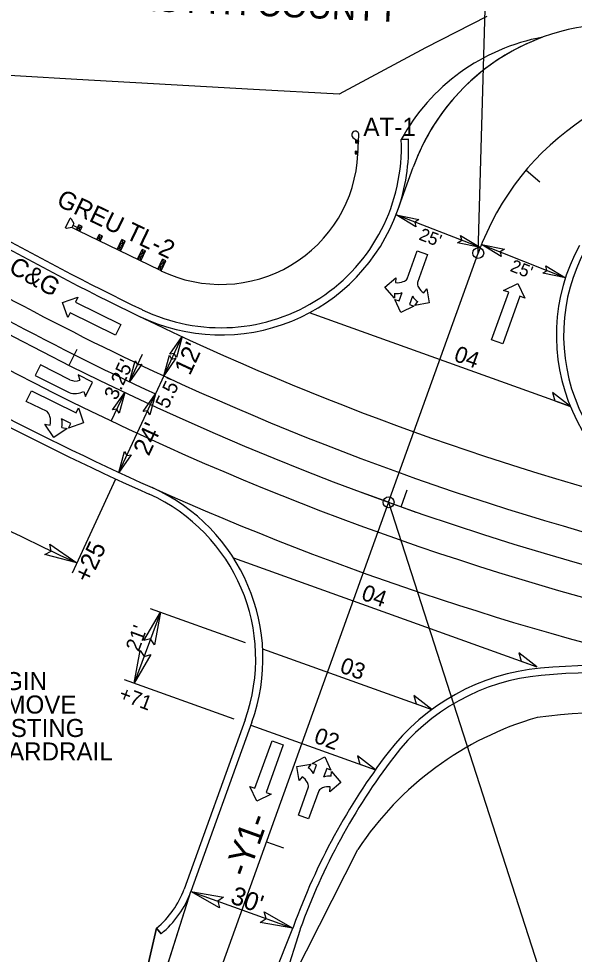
# Model space of a CAD drawing. Extents: x 1616561 to 1622460, y 896726 to 899651.
# Drawn here: x 1619426.3 to 1619580.2, y 897963.2 to 898222.4 of the extents above; entities that cross this region are included whole.
import ezdxf

# ---------------------------------------------------------------- set-up
doc = ezdxf.new("R2010")
doc.units = 0
for name, color, linetype in [('Old_Level_3', 7, 'Continuous'), ('Prop Dimension', 7, 'Continuous'), ('Prop DSN Text', 7, 'Continuous'), ('Prop Guardrail', 7, 'Continuous'), ('Prop Guardrail Anchor Unit CELL', 7, 'Continuous'), ('Prop Horizontal Alignment', 7, 'Continuous'), ('Prop Horizontal Alignment Tick Small', 7, 'Continuous'), ('Prop Lane Arrow CELL', 7, 'Continuous'), ('Prop North Arrow NAD83 for Plan Sheets CELL', 7, 'Continuous'), ('Prop Rem of Exist Asph Pvmt', 7, 'Continuous'), ('Prop Shade Light', 7, 'Continuous'), ('Prop Superelevation  Arrow CELL', 7, 'Continuous'), ('Prop Superelevation Label', 7, 'Continuous'), ('Prop Terminator CELL', 7, 'Continuous'), ('Scratch_Level_1', 7, 'Continuous'), ('Sheet Cutting Line CELL', 7, 'Continuous'), ('Sheet North Arrow CELL', 7, 'Continuous'), ('Sheet Sticker Preliminary CELL', 7, 'Continuous')]:
    doc.layers.add(name, color=color, linetype=linetype)

msp = doc.modelspace()

# ---------------------------------------------------------------- linework, layer by layer
at = {"layer": 'Old_Level_3'}
msp.add_line((1619466.5, 898123.48), (1619464.18, 898118.49), dxfattribs=at)
for radius, start, end in [(791.25, 230.78618, 245.11013), (808.75, 229.34838, 255.58792), (796.75, 230.7866, 245.11013), (779.25, 244.13867, 256.29422), (791.25, 245.11013, 270), (820.75, 245.81358, 257.75937)]:
    msp.add_arc((1619799.51, 898841.24), radius, start, end, dxfattribs=at)
at = {"layer": 'Prop Dimension'}
for p, q in [((1619554.16, 898159.09), (1619530.83, 898168.07)), ((1619554.49, 898159.91), (1619577.71, 898150.66)), ((1619466.5, 898123.48), (1619471.55, 898134.37)), ((1619457.02, 898121.86), (1619460.56, 898129.47)), ((1619451.96, 898110.94), (1619455.66, 898118.91)), ((1619454.08, 898096.72), (1619464.18, 898118.49)), ((1619441.18, 898068.92), (1619453.24, 898094.91)), ((1619474.01, 897980.62), (1619502.24, 897970.46))]:
    msp.add_line(p, q, dxfattribs=at)
msp.add_arc((1619799.51, 898841.24), 848.4, 239.73865, 245.11013, dxfattribs=at)
at = {"layer": 'Prop Guardrail'}
msp.add_line((1619496.51, 897945.53), (1619520.23, 897992.28), dxfattribs=at)
for centre, radius, start, end in [((1619482.29, 898186.82), 38, 244.1387, 357.2224), ((1619594.68, 897943.19), 89.17, 106.1694, 146.5997), ((1619590.52, 897870.95), 159.23, 78.786, 97.4583)]:
    msp.add_arc(centre, radius, start, end, dxfattribs=at)
at = {"layer": 'Prop Guardrail Anchor Unit CELL'}
for p, q in [((1619518.88, 898189.52), (1619519.81, 898188.75)), ((1619520.42, 898188.52), (1619520.5, 898190.24)), ((1619519.62, 898188.76), (1619519.59, 898188.06)), ((1619520.43, 898188.72), (1619519.59, 898188.06)), ((1619519.59, 898188.06), (1619520.39, 898188.02)), ((1619520.43, 898188.72), (1619519.62, 898188.76)), ((1619520.39, 898188.02), (1619519.62, 898188.76)), ((1619520.43, 898188.72), (1619520.08, 898188.74)), ((1619520.43, 898188.72), (1619520.08, 898188.74)), ((1619520.25, 898184.98), (1619520.42, 898188.52)), ((1619520.39, 898188.02), (1619520.43, 898188.72)), ((1619520.42, 898188.59), (1619520.41, 898188.46)), ((1619520.42, 898188.59), (1619520.41, 898188.46)), ((1619519.47, 898185.72), (1619519.44, 898185.02)), ((1619520.28, 898185.68), (1619519.44, 898185.02)), ((1619519.44, 898185.02), (1619520.25, 898184.98)), ((1619520.28, 898185.68), (1619519.47, 898185.72)), ((1619520.25, 898184.98), (1619519.47, 898185.72)), ((1619520.25, 898184.98), (1619520.28, 898185.68)), ((1619439.29, 898164.5), (1619440.58, 898167.14)), ((1619440.85, 898167.01), (1619440.58, 898167.14)), ((1619440.85, 898167.01), (1619441.54, 898165.72)), ((1619439.57, 898164.36), (1619439.29, 898164.5)), ((1619441, 898164.62), (1619439.57, 898164.36)), ((1619441.54, 898165.72), (1619441, 898164.62)), ((1619442.32, 898163.98), (1619441, 898164.62)), ((1619441.32, 898165.27), (1619442.64, 898164.63)), ((1619442.32, 898163.97), (1619442.98, 898165.34)), ((1619443.88, 898164.9), (1619442.32, 898163.97)), ((1619443.22, 898163.53), (1619442.32, 898163.97)), ((1619442.77, 898163.75), (1619465.27, 898152.85)), ((1619443.88, 898164.9), (1619442.98, 898165.34)), ((1619443.22, 898163.53), (1619442.98, 898165.34)), ((1619443.22, 898163.53), (1619443.88, 898164.9)), ((1619447.94, 898161.24), (1619448.61, 898162.61)), ((1619449.51, 898162.17), (1619447.94, 898161.24)), ((1619448.84, 898160.81), (1619447.94, 898161.24)), ((1619449.51, 898162.17), (1619448.61, 898162.61)), ((1619448.84, 898160.81), (1619448.61, 898162.61)), ((1619448.84, 898160.81), (1619449.51, 898162.17)), ((1619453.57, 898158.52), (1619454.89, 898161.25)), ((1619454.23, 898159.88), (1619455.79, 898160.81)), ((1619454.47, 898158.08), (1619455.79, 898160.81)), ((1619455.79, 898160.81), (1619454.89, 898161.25)), ((1619454.89, 898161.25), (1619455.13, 898159.45)), ((1619455.13, 898159.45), (1619453.57, 898158.52)), ((1619454.47, 898158.08), (1619453.57, 898158.52)), ((1619455.13, 898159.45), (1619454.23, 898159.88)), ((1619454.47, 898158.08), (1619454.23, 898159.88)), ((1619459.19, 898155.79), (1619460.52, 898158.52)), ((1619461.42, 898158.09), (1619460.52, 898158.52)), ((1619460.52, 898158.52), (1619460.75, 898156.72)), ((1619460.75, 898156.72), (1619459.19, 898155.79)), ((1619460.09, 898155.35), (1619459.19, 898155.79)), ((1619459.85, 898157.16), (1619461.42, 898158.09)), ((1619460.75, 898156.72), (1619459.85, 898157.16)), ((1619460.09, 898155.35), (1619459.85, 898157.16)), ((1619460.09, 898155.35), (1619461.42, 898158.09)), ((1619464.82, 898153.06), (1619466.14, 898155.8)), ((1619467.04, 898155.36), (1619466.14, 898155.8)), ((1619466.14, 898155.8), (1619466.38, 898153.99)), ((1619466.38, 898153.99), (1619464.82, 898153.06)), ((1619465.72, 898152.63), (1619464.82, 898153.06)), ((1619465.48, 898154.43), (1619467.04, 898155.36)), ((1619466.38, 898153.99), (1619465.48, 898154.43)), ((1619465.72, 898152.63), (1619465.48, 898154.43)), ((1619465.72, 898152.63), (1619467.04, 898155.36))]:
    msp.add_line(p, q, dxfattribs=at)
msp.add_ellipse((1619519.51, 898190.29), major_axis=(-0.992, 0.048), ratio=0.995379, start_param=3.141593, end_param=7.214552, dxfattribs=at)
at = {"layer": 'Prop Horizontal Alignment'}
for p, q in [((1619532.25, 898188.96), (1619534.24, 898189.05)), ((1619449.19, 897903.92), (1619464.48, 897970.44)), ((1619464.48, 897970.44), (1619465.75, 897968.9))]:
    msp.add_line(p, q, dxfattribs=at)
for centre, radius, start, end in [((1619581.52, 898162.12), 56.11, 100.4391, 151.4276), ((1619482.29, 898186.82), 52, 340.2164, 2.4498), ((1619448.6, 897989.76), 27, 309.4241, 340.2164)]:
    msp.add_arc(centre, radius, start, end, dxfattribs=at)
at = {"layer": 'Prop Horizontal Alignment Tick Small'}
for p, q in [((1619534.24, 898189.05), (1619532.25, 898188.96)), ((1619488.99, 898028.18), (1619472.13, 897981.29)), ((1619465.75, 897968.9), (1619464.48, 897970.44)), ((1619504.12, 897969.79), (1619496.51, 897945.53)), ((1619504.3, 897970.28), (1619504.12, 897969.79))]:
    msp.add_line(p, q, dxfattribs=at)
for centre, radius, start, end in [((1619799.51, 898841.24), 777.25, 229.34838, 244.13867), ((1619799.51, 898841.24), 822.75, 230.21163, 245.81358), ((1619482.29, 898186.82), 50, 244.1387, 2.4498), ((1619627.2, 898134.7), 50, 151.351, 256.2942), ((1619441.94, 898045.1), 50, 340.2164, 65.8136), ((1619576.32, 897982.74), 58, 95.2664, 142.7094), ((1619587.34, 897863.24), 178, 77.7594, 95.2664), ((1619671.79, 897910.03), 178, 142.7094, 160.2164), ((1619448.6, 897989.76), 25, 309.4241, 340.2164)]:
    msp.add_arc(centre, radius, start, end, dxfattribs=at)
at = {"layer": 'Prop Lane Arrow CELL'}
for p, q in [((1619533.88, 898150.39), (1619536.67, 898158.14)), ((1619536.67, 898158.14), (1619539.51, 898157.12)), ((1619539.51, 898157.12), (1619536.71, 898149.32)), ((1619527.72, 898148.1), (1619530.75, 898150.64)), ((1619530.75, 898150.64), (1619530.69, 898149.31)), ((1619530.35, 898145.03), (1619527.72, 898148.1)), ((1619560.59, 898147.16), (1619564.57, 898149.07)), ((1619564.57, 898149.07), (1619566.51, 898145.02)), ((1619438.45, 898143.81), (1619442.69, 898145.29)), ((1619442.69, 898145.29), (1619442.03, 898143.94)), ((1619530.41, 898146.36), (1619530.35, 898145.03)), ((1619531.67, 898144.25), (1619532.53, 898146.63)), ((1619535.35, 898145.56), (1619534.51, 898143.22)), ((1619538.49, 898146.51), (1619539.29, 898147.57)), ((1619539.29, 898147.57), (1619539.97, 898143.69)), ((1619557.26, 898133.48), (1619562, 898146.65)), ((1619565.1, 898145.53), (1619560.36, 898132.36)), ((1619562, 898146.65), (1619560.59, 898147.16)), ((1619566.51, 898145.02), (1619565.1, 898145.53)), ((1619439.91, 898139.64), (1619438.45, 898143.81)), ((1619442.03, 898143.94), (1619454.59, 898137.76)), ((1619532.16, 898141.01), (1619530.48, 898144.67)), ((1619530.48, 898144.67), (1619531.67, 898144.25)), ((1619535.71, 898142.79), (1619532.16, 898141.01)), ((1619534.51, 898143.22), (1619535.71, 898142.79)), ((1619536.03, 898142.99), (1619536.83, 898144.05)), ((1619539.97, 898143.69), (1619536.03, 898142.99)), ((1619440.57, 898140.98), (1619439.91, 898139.64)), ((1619453.13, 898134.8), (1619440.57, 898140.98)), ((1619454.59, 898137.76), (1619453.13, 898134.8)), ((1619560.36, 898132.36), (1619557.26, 898133.48)), ((1619432.31, 898126.51), (1619430.84, 898123.56)), ((1619440.5, 898122.43), (1619432.31, 898126.51)), ((1619430.84, 898123.56), (1619440.28, 898118.85)), ((1619446.79, 898121.7), (1619442.78, 898123.75)), ((1619442.78, 898123.75), (1619443.25, 898122.34)), ((1619428.38, 898116.41), (1619429.83, 898119.37)), ((1619429.83, 898119.37), (1619442.21, 898113.28)), ((1619444.78, 898117.79), (1619446.79, 898121.7)), ((1619444.31, 898119.19), (1619444.78, 898117.79)), ((1619434.16, 898113.57), (1619428.38, 898116.41)), ((1619442.21, 898113.28), (1619442.88, 898114.63)), ((1619442.88, 898114.63), (1619444.27, 898110.43)), ((1619440.76, 898110.32), (1619438.2, 898111.58)), ((1619436.06, 898106.44), (1619433.58, 898110.12)), ((1619433.58, 898110.12), (1619435.01, 898109.86)), ((1619439.74, 898108.93), (1619436.06, 898106.44)), ((1619438.26, 898109.21), (1619439.74, 898108.93)), ((1619444.27, 898110.43), (1619440.09, 898108.97)), ((1619440.09, 898108.97), (1619440.76, 898110.32)), ((1619491.74, 898009.2), (1619496.48, 898022.37)), ((1619499.59, 898021.26), (1619494.85, 898008.08)), ((1619496.48, 898022.37), (1619499.59, 898021.26)), ((1619503.3, 898015.21), (1619507.23, 898015.92)), ((1619507.23, 898015.92), (1619506.44, 898014.86)), ((1619507.56, 898016.11), (1619511.1, 898017.89)), ((1619508.75, 898015.68), (1619507.56, 898016.11)), ((1619507.91, 898013.34), (1619508.75, 898015.68)), ((1619511.1, 898017.89), (1619512.79, 898014.23)), ((1619503.98, 898011.34), (1619503.3, 898015.21)), ((1619511.6, 898014.66), (1619510.74, 898012.27)), ((1619512.79, 898014.23), (1619511.6, 898014.66)), ((1619512.86, 898012.55), (1619512.92, 898013.87)), ((1619512.92, 898013.87), (1619515.55, 898010.8)), ((1619504.78, 898012.4), (1619503.98, 898011.34)), ((1619515.55, 898010.8), (1619512.51, 898008.27)), ((1619492.28, 898005.66), (1619490.33, 898009.71)), ((1619490.33, 898009.71), (1619491.74, 898009.2)), ((1619494.85, 898008.08), (1619496.26, 898007.57)), ((1619503.75, 898001.78), (1619506.56, 898009.58)), ((1619509.39, 898008.51), (1619506.6, 898000.76)), ((1619512.51, 898008.27), (1619512.57, 898009.59)), ((1619496.26, 898007.57), (1619492.28, 898005.66)), ((1619506.6, 898000.76), (1619503.75, 898001.78))]:
    msp.add_line(p, q, dxfattribs=at)
for centre, radius, start, end in [((1619532.04, 898151.74), 2.28, 289.2896, 324.0556), ((1619531.25, 898153.28), 4, 261.8495, 292.7797), ((1619538.98, 898149.24), 2.28, 178.1454, 211.1433), ((1619540.57, 898149.92), 4, 207.6532, 238.8659), ((1619531, 898150.31), 4, 261.4803, 292.37), ((1619538.87, 898147.48), 4, 208.4597, 239.2361), ((1619441.96, 898125.34), 3.28, 243.5163, 293.1745), ((1619441.88, 898123.84), 5.25, 252.1924, 297.5041), ((1619432.51, 898111.66), 2.52, 12.8702, 49.1822), ((1619430.72, 898110.97), 4.43, 345.5068, 16.3603), ((1619433.96, 898110.33), 4.43, 345.388, 16.2666), ((1619504.4, 898011.43), 4, 28.4597, 59.2361), ((1619502.7, 898008.98), 4, 27.6532, 58.8659), ((1619504.29, 898009.66), 2.28, 358.1454, 31.1433), ((1619512.27, 898008.6), 4, 81.4803, 112.37), ((1619511.23, 898007.16), 2.28, 109.2896, 144.0556), ((1619512.02, 898005.63), 4, 81.8495, 112.7797)]:
    msp.add_arc(centre, radius, start, end, dxfattribs=at)
at = {"layer": 'Prop North Arrow NAD83 for Plan Sheets CELL'}
for points in [[(1619579.08, 898114.98), (1619574.12, 898118.9), (1619574.73, 898116.55)], [(1619569.78, 898042.88), (1619564.81, 898046.79), (1619565.43, 898044.44)], [(1619540.7, 898031.02), (1619535.73, 898034.93), (1619536.35, 898032.58)], [(1619525.08, 898014.32), (1619520.11, 898018.23), (1619520.73, 898015.89)]]:
    msp.add_lwpolyline(points, close=True, dxfattribs=at)
at = {"layer": 'Prop Rem of Exist Asph Pvmt'}
for p, q in [((1619555.96, 898223.09), (1619538.96, 898214.39)), ((1619538.96, 898214.39), (1619515.06, 898201.52))]:
    msp.add_line(p, q, dxfattribs=at)
msp.add_lwpolyline([(1619515.06, 898201.52), (1619491.31, 898202.8), (1619473.44, 898203.85), (1619442.37, 898205.63), (1619411.08, 898207.46), (1619398.89, 898207.97)], dxfattribs=at)
at = {"layer": 'Prop Shade Light'}
for p, q in [((1619532.25, 898188.96), (1619534.24, 898189.05)), ((1619531.22, 898169.22), (1619535.56, 898181.28)), ((1619464.48, 897970.44), (1619449.19, 897903.92)), ((1619465.75, 897968.9), (1619464.48, 897970.44))]:
    msp.add_line(p, q, dxfattribs=at)
msp.add_lwpolyline([(1619451.1, 897908.57), (1619453.08, 897914.8), (1619474.01, 897980.62)], dxfattribs=at)
for centre, radius, start, end in [((1619581.52, 898162.12), 56.11, 100.4391, 151.4276), ((1619592.02, 898160.98), 60, 110.1442, 160.2164), ((1619482.29, 898186.82), 52, 340.2164, 2.4498), ((1619448.6, 897989.76), 27, 309.4241, 340.2164)]:
    msp.add_arc(centre, radius, start, end, dxfattribs=at)
at = {"layer": 'Prop Superelevation  Arrow CELL'}
for p, q in [((1619566.79, 898180.45), (1619570.62, 898177.23)), ((1619440.3, 898126.42), (1619442.55, 898130.89)), ((1619532.23, 898087.21), (1619533.9, 898091.93)), ((1619494.89, 897994.36), (1619499.6, 897992.67))]:
    msp.add_line(p, q, dxfattribs=at)
at = {"layer": 'Prop Superelevation Label'}
for q in [(1619521.21, 898091.17), (1619536.27, 898085.75)]:
    msp.add_line((1619528.74, 898088.46), q, dxfattribs=at)
at = {"layer": 'Prop Terminator CELL'}
for p, q in [((1619531.22, 898169.22), (1619535.56, 898181.28)), ((1619490.87, 898027.5), (1619474.01, 897980.62)), ((1619451.1, 897908.57), (1619474.01, 897980.62)), ((1619472.34, 897896.2), (1619502.24, 897970.46)), ((1619502.41, 897970.96), (1619502.24, 897970.46))]:
    msp.add_line(p, q, dxfattribs=at)
for points in [[(1619536.32, 898164.79), (1619530.83, 898168.07), (1619537.15, 898166.84), (1619535.99, 898166.08)], [(1619548.67, 898162.36), (1619554.16, 898159.09), (1619547.85, 898160.32), (1619549, 898161.07)], [(1619559.94, 898156.57), (1619554.49, 898159.91), (1619560.79, 898158.61), (1619559.62, 898157.87)], [(1619572.26, 898154), (1619577.71, 898150.66), (1619571.41, 898151.96), (1619572.57, 898152.7)], [(1619468.17, 898129.49), (1619471.55, 898134.37), (1619470.01, 898128.59), (1619469.39, 898129.71)], [(1619460.4, 898126.74), (1619457.02, 898121.86), (1619458.56, 898127.63), (1619459.19, 898126.52)], [(1619469.87, 898128.37), (1619466.5, 898123.48), (1619468.03, 898129.26), (1619468.66, 898128.14)], [(1619452.28, 898114.03), (1619455.66, 898118.91), (1619454.12, 898113.14), (1619453.5, 898114.25)], [(1619460.8, 898113.61), (1619464.18, 898118.49), (1619462.65, 898112.72), (1619462.02, 898113.84)], [(1619457.46, 898101.61), (1619454.08, 898096.72), (1619455.61, 898102.5), (1619456.24, 898101.38)], [(1619434.93, 898076.83), (1619442.44, 898071.64), (1619433.56, 898074), (1619435.28, 898074.96)], [(1619461, 898050.14), (1619465.56, 898058.05), (1619463.94, 898049), (1619462.83, 898050.63)], [(1619462.87, 898046.25), (1619458.31, 898038.34), (1619459.93, 898047.38), (1619461.04, 898045.75)], [(1619481.95, 897976.11), (1619474.01, 897980.62), (1619483.07, 897979.06), (1619481.44, 897977.94)], [(1619494.29, 897974.97), (1619502.24, 897970.46), (1619493.18, 897972.02), (1619494.8, 897973.14)]]:
    msp.add_lwpolyline(points, close=True, dxfattribs=at)
for centre, radius, start, end in [((1619799.51, 898841.24), 779.25, 229.34838, 244.13867), ((1619592.02, 898160.98), 60, 86.8045, 160.2164), ((1619799.51, 898841.24), 820.75, 230.21163, 245.81358), ((1619482.29, 898186.82), 52, 244.1387, 340.2164), ((1619627.2, 898134.7), 52, 151.351, 256.2942), ((1619441.94, 898045.1), 52, 340.2164, 65.8136), ((1619576.32, 897982.74), 60, 95.2664, 142.7094), ((1619587.34, 897863.24), 180, 77.7594, 95.2664), ((1619671.79, 897910.03), 180, 142.7094, 160.2164)]:
    msp.add_arc(centre, radius, start, end, dxfattribs=at)
at = {"layer": 'Sheet Cutting Line CELL'}
for q in [(1619553.58, 898157.53), (1619460.07, 897897.55)]:
    msp.add_line((1619528.74, 898088.46), q, dxfattribs=at)
for centre, radius, start, end in [((1619799.51, 898841.24), 800, 229.34838, 270), ((1619624.16, 898132.14), 75, 86.8045, 160.2164)]:
    msp.add_arc(centre, radius, start, end, dxfattribs=at)
at = {"layer": 'Sheet North Arrow CELL'}
for p, q in [((1619553.58, 898157.53), (1619558.52, 898336.82)), ((1619528.74, 898088.46), (1619598.19, 897873.05))]:
    msp.add_line(p, q, dxfattribs=at)
for centre in [(1619553.58, 898157.53), (1619528.74, 898088.46)]:
    msp.add_circle(centre, 1.5, dxfattribs=at)
at = {"layer": 'Sheet Sticker Preliminary CELL'}
for p, q in [((1619579.08, 898114.98), (1619506.83, 898140.97)), ((1619485.76, 898073.1), (1619569.78, 898042.88)), ((1619465.56, 898058.05), (1619458.31, 898038.34)), ((1619462.74, 898059.06), (1619489, 898049.62)), ((1619493.87, 898047.86), (1619540.7, 898031.02)), ((1619455.48, 898039.35), (1619485.88, 898028.42)), ((1619490.59, 898026.73), (1619525.08, 898014.32))]:
    msp.add_line(p, q, dxfattribs=at)

# ---------------------------------------------------------------- texts
at = {"layer": 'Prop Dimension'}
for s, height, rotation, p in [('2\'-6" C&G', 5.044, 330.6111, (1619409.86, 898159.91)), ("25'", 3.5, 338.9436, (1619536.88, 898161.31)), ("25'", 3.5, 338.2654, (1619562.13, 898152.61)), ("12'", 5, 65.1101, (1619473.7, 898123.36)), ("3.25'", 4, 65.1101, (1619453.38, 898116.53)), ("5.5'", 4, 65.1101, (1619467.61, 898114.12)), ("24'", 5, 65.1101, (1619462.33, 898101.05)), ('+25', 5, 64.968, (1619445.86, 898065.8)), ("30'", 5.044, 340.2164, (1619484.64, 897977.48))]:
    msp.add_text(s, height=height, rotation=rotation, dxfattribs=at).set_placement(p)
at = {"layer": 'Prop DSN Text'}
msp.add_text('FORSYTH COUNTY', height=7, rotation=357.4583, dxfattribs=at).set_placement((1619444.85, 898225.36))
for s, p in [('BEGIN', (1619413.34, 898036.42)), ('REMOVE', (1619413.34, 898029.92)), ('EXISTING', (1619413.34, 898023.42)), ('GUARDRAIL', (1619413.34, 898016.92))]:
    msp.add_text(s, height=5, dxfattribs=at).set_placement(p)
at = {"layer": 'Prop Guardrail Anchor Unit CELL'}
msp.add_text('AT-1', height=5, dxfattribs=at).set_placement((1619521.76, 898189.99))
msp.add_text('GREU TL-2', height=5, rotation=334.427, dxfattribs=at).set_placement((1619436.47, 898170.85))
at = {"layer": 'Scratch_Level_1'}
msp.add_text('-Y1-', height=7, rotation=70.2164, dxfattribs=at).set_placement((1619489.68, 897984.26))
at = {"layer": 'Sheet Sticker Preliminary CELL'}
for s, height, rotation, p in [('04', 4.5, 340.2164, (1619546.54, 898127.73)), ('04', 4.5, 340.2164, (1619520.89, 898061.59)), ("21'", 4, 69.7886, (1619459.55, 898046.86)), ('03', 4.5, 340.2164, (1619514.95, 898041.42)), ('+71', 4, 339.4232, (1619453.77, 898033.87)), ('02', 4.5, 340.2164, (1619507.78, 898021.96))]:
    msp.add_text(s, height=height, rotation=rotation, dxfattribs=at).set_placement(p)

doc.saveas('drawing.dxf')
